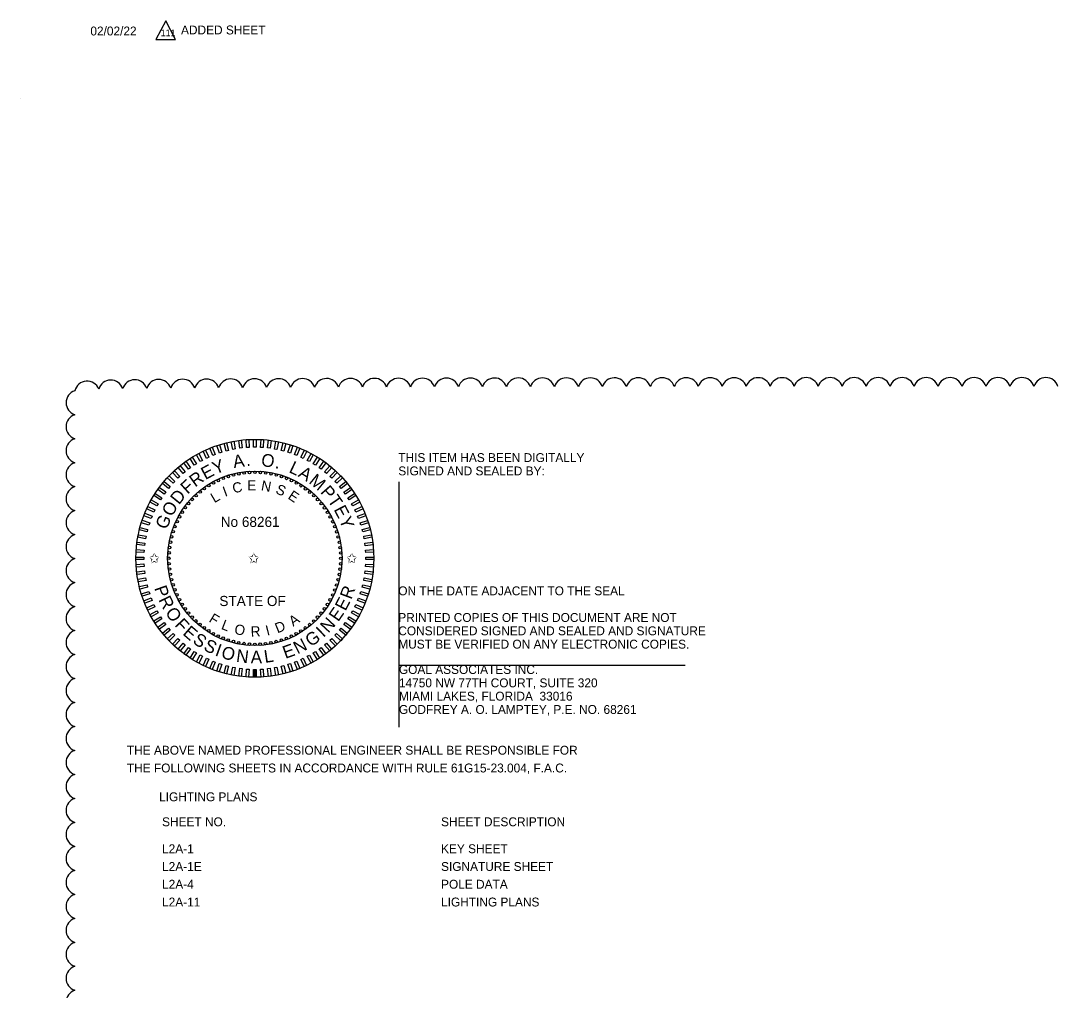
# Model space of a CAD drawing. Extents: x -811 to 10319, y -2309 to 9962.
# Drawn here: x -811.34 to -803.18, y -2252.59 to -2244.95 of the extents above; entities that cross this region are included whole.
import ezdxf

# ---------------------------------------------------------------- set-up
doc = ezdxf.new("R2010")
doc.units = 0
for name, color, linetype in [('AdhocPoint_dp', 7, 'Continuous'), ('PlotBorder_dp', 7, 'Continuous'), ('ScratchEle_dp', 7, 'Continuous'), ('SheetBorder_dp', 7, 'Continuous'), ('TextMinor', 7, 'Continuous'), ('TextMisc', 7, 'Continuous'), ('TextShtNo', 7, 'Continuous'), ('TextTitle', 7, 'Continuous')]:
    doc.layers.add(name, color=color, linetype=linetype)

msp = doc.modelspace()

# ---------------------------------------------------------------- linework, layer by layer
at = {"layer": 'AdhocPoint_dp'}
for p, q in [((-808.3546, -2248.5853), (-808.3546, -2250.52)), ((-808.3546, -2250.03), (-806.0979, -2250.03))]:
    msp.add_line(p, q, dxfattribs=at)
at = {"layer": 'ScratchEle_dp'}
for centre, radius, start, end in [((-810.8128, -2247.8912), 0.0992, 21.52097, 166.52097), ((-810.6255, -2247.883), 0.0991, 18.44241, 163.44241), ((-810.4367, -2247.8804), 0.0991, 18.17187, 163.17187), ((-810.2478, -2247.8784), 0.0991, 18.03188, 163.03188), ((-810.0588, -2247.8768), 0.0991, 17.94243, 162.94243), ((-809.8699, -2247.8754), 0.0991, 17.8789, 162.8789), ((-809.6809, -2247.8743), 0.0991, 17.83076, 162.83076), ((-809.4919, -2247.8732), 0.0991, 17.79266, 162.79266), ((-809.3029, -2247.8723), 0.0991, 17.76151, 162.76151), ((-809.1139, -2247.8715), 0.0991, 17.73544, 162.73544), ((-808.9249, -2247.8708), 0.0991, 17.7132, 162.7132), ((-808.736, -2247.8701), 0.0991, 17.69393, 162.69393), ((-808.547, -2247.8695), 0.0991, 17.67702, 162.67702), ((-808.358, -2247.8689), 0.0991, 17.66204, 162.66204), ((-808.169, -2247.8684), 0.0991, 17.64863, 162.64863), ((-807.98, -2247.8679), 0.0991, 17.63655, 162.63655), ((-807.791, -2247.8675), 0.0991, 17.62558, 162.62558), ((-807.602, -2247.8671), 0.0991, 17.61556, 162.61556), ((-807.413, -2247.8668), 0.0991, 17.60637, 162.60637), ((-807.224, -2247.8664), 0.0991, 17.5979, 162.5979), ((-807.035, -2247.8661), 0.0991, 17.59006, 162.59006), ((-806.846, -2247.8658), 0.0991, 17.58277, 162.58277), ((-806.657, -2247.8656), 0.0991, 17.57597, 162.57597), ((-806.468, -2247.8653), 0.0991, 17.56961, 162.56961), ((-806.279, -2247.8651), 0.0991, 17.56364, 162.56364), ((-806.09, -2247.8649), 0.0991, 17.55803, 162.55803), ((-805.901, -2247.8647), 0.0991, 17.55274, 162.55274), ((-805.712, -2247.8645), 0.0991, 17.54774, 162.54774), ((-805.523, -2247.8644), 0.0991, 17.54301, 162.54301), ((-805.334, -2247.8643), 0.0991, 17.53852, 162.53852), ((-805.145, -2247.8641), 0.0991, 17.53425, 162.53425), ((-804.956, -2247.864), 0.0991, 17.53018, 162.53018), ((-804.767, -2247.8639), 0.0991, 17.52631, 162.52631), ((-804.578, -2247.8639), 0.0991, 17.52261, 162.52261), ((-804.389, -2247.8638), 0.0991, 17.51907, 162.51907), ((-804.2, -2247.8637), 0.0991, 17.51569, 162.51569), ((-804.011, -2247.8637), 0.0991, 17.51244, 162.51244), ((-803.8221, -2247.8637), 0.0991, 17.50933, 162.50933), ((-803.6331, -2247.8636), 0.0991, 17.50633, 162.50633), ((-803.4441, -2247.8636), 0.0991, 17.50345, 162.50345), ((-803.2551, -2247.8636), 0.0991, 17.50077, 162.50077), ((-810.8794, -2247.9625), 0.099, 107.5, 252.5), ((-810.8794, -2248.1514), 0.0991, 107.5, 252.5), ((-810.8794, -2248.3405), 0.0991, 107.5, 252.5), ((-810.8794, -2248.5295), 0.0991, 107.5, 252.5), ((-810.8794, -2248.7185), 0.0991, 107.5, 252.5), ((-810.8794, -2248.9075), 0.0991, 107.5, 252.5), ((-810.8794, -2249.0965), 0.0991, 107.5, 252.5), ((-810.8794, -2249.2855), 0.0991, 107.5, 252.5), ((-810.8794, -2249.4745), 0.0991, 107.5, 252.5), ((-810.8794, -2249.6635), 0.0991, 107.5, 252.5), ((-810.8794, -2249.8525), 0.0991, 107.5, 252.5), ((-810.8794, -2250.0415), 0.0991, 107.5, 252.5), ((-810.8794, -2250.2305), 0.0991, 107.5, 252.5), ((-810.8794, -2250.4195), 0.0991, 107.5, 252.5), ((-810.8794, -2250.6085), 0.0991, 107.5, 252.5), ((-810.8794, -2250.7975), 0.0991, 107.5, 252.5), ((-810.8794, -2250.9865), 0.0991, 107.5, 252.5), ((-810.8794, -2251.1755), 0.0991, 107.5, 252.5), ((-810.8794, -2251.3645), 0.0991, 107.5, 252.5), ((-810.8794, -2251.5535), 0.0991, 107.5, 252.5), ((-810.8794, -2251.7425), 0.0991, 107.5, 252.5), ((-810.8794, -2251.9315), 0.0991, 107.5, 252.5), ((-810.8794, -2252.1205), 0.0991, 107.5, 252.5), ((-810.8794, -2252.3095), 0.0991, 107.5, 252.5), ((-810.8794, -2252.4985), 0.0991, 107.50047, 252.50047), ((-810.8794, -2252.6874), 0.0991, 107.52584, 252.52584)]:
    msp.add_arc(centre, radius, start, end, dxfattribs=at)
at = {"layer": 'SheetBorder_dp'}
msp.add_line((-811.3358, -2245.5621), (-811.3358, -2245.5621), dxfattribs=at)
at = {"layer": 'TextMinor'}
for radius in [0.9375, 0.6875]:
    msp.add_circle((-809.4901, -2249.1887), radius, dxfattribs=at)
at = {"layer": 'TextMisc'}
msp.add_lwpolyline([(-810.1928, -2244.9521), (-810.2698, -2245.1004), (-810.1158, -2245.1004)], close=True, dxfattribs=at)
at = {"layer": 'TextShtNo'}
for p, q in [((-809.5001, -2250.1262), (-809.5003, -2250.0637)), ((-809.4901, -2250.1262), (-809.4903, -2250.0637)), ((-809.4801, -2250.1261), (-809.4803, -2250.0636))]:
    msp.add_line(p, q, dxfattribs=at)
for points in [[(-809.4799, -2248.3136), (-809.5001, -2248.3136), (-809.5001, -2248.2512), (-809.4799, -2248.2512)], [(-809.8028, -2248.3713), (-809.8215, -2248.3788), (-809.8445, -2248.3207), (-809.8258, -2248.3133)], [(-809.7508, -2248.3533), (-809.77, -2248.3596), (-809.7893, -2248.3002), (-809.7701, -2248.2939)], [(-809.6979, -2248.3386), (-809.7174, -2248.3436), (-809.7329, -2248.2831), (-809.7134, -2248.2781)], [(-809.6441, -2248.3272), (-809.6639, -2248.331), (-809.6756, -2248.2697), (-809.6558, -2248.2659)], [(-809.5897, -2248.3193), (-809.6097, -2248.3218), (-809.6175, -2248.2599), (-809.5975, -2248.2573)], [(-809.5349, -2248.3147), (-809.555, -2248.316), (-809.559, -2248.2537), (-809.5388, -2248.2524)], [(-809.425, -2248.316), (-809.4452, -2248.3147), (-809.4412, -2248.2524), (-809.4211, -2248.2537)], [(-809.3703, -2248.3218), (-809.3904, -2248.3193), (-809.3825, -2248.2573), (-809.3625, -2248.2599)], [(-809.3162, -2248.3311), (-809.336, -2248.3273), (-809.3243, -2248.2659), (-809.3045, -2248.2697)], [(-809.2626, -2248.3437), (-809.2822, -2248.3387), (-809.2667, -2248.2782), (-809.2471, -2248.2832)], [(-809.21, -2248.3596), (-809.2292, -2248.3534), (-809.2099, -2248.294), (-809.1907, -2248.3002)], [(-809.1585, -2248.3788), (-809.1773, -2248.3714), (-809.1543, -2248.3134), (-809.1355, -2248.3208)], [(-809.9504, -2248.4444), (-809.9674, -2248.4552), (-810.0009, -2248.4025), (-809.9838, -2248.3917)], [(-809.9027, -2248.417), (-809.9204, -2248.4267), (-809.9505, -2248.372), (-809.9328, -2248.3623)], [(-809.8535, -2248.3926), (-809.8717, -2248.4012), (-809.8983, -2248.3447), (-809.8801, -2248.3361)], [(-809.1083, -2248.4013), (-809.1266, -2248.3927), (-809.1, -2248.3362), (-809.0817, -2248.3448)], [(-809.0596, -2248.4268), (-809.0773, -2248.4171), (-809.0473, -2248.3624), (-809.0296, -2248.3721)], [(-809.0127, -2248.4553), (-809.0297, -2248.4445), (-808.9962, -2248.3918), (-808.9792, -2248.4026)], [(-810.04, -2248.508), (-810.0556, -2248.5208), (-810.0954, -2248.4727), (-810.0798, -2248.4599)], [(-809.9962, -2248.4748), (-810.0125, -2248.4866), (-810.0492, -2248.4361), (-810.0329, -2248.4243)], [(-808.9676, -2248.4868), (-808.9839, -2248.4749), (-808.9472, -2248.4244), (-808.9308, -2248.4362)], [(-808.9245, -2248.5209), (-808.9401, -2248.5081), (-808.9003, -2248.46), (-808.8847, -2248.4728)], [(-810.121, -2248.5823), (-810.1348, -2248.597), (-810.1804, -2248.5542), (-810.1665, -2248.5395)], [(-810.0817, -2248.5438), (-810.0964, -2248.5577), (-810.1392, -2248.5121), (-810.1244, -2248.4983)], [(-808.8837, -2248.5578), (-808.8984, -2248.544), (-808.8557, -2248.4984), (-808.841, -2248.5123)], [(-808.8453, -2248.5971), (-808.8591, -2248.5824), (-808.8136, -2248.5396), (-808.7998, -2248.5544)], [(-810.192, -2248.6661), (-810.2039, -2248.6824), (-810.2544, -2248.6457), (-810.2426, -2248.6294)], [(-810.1579, -2248.6231), (-810.1707, -2248.6386), (-810.2188, -2248.5988), (-810.206, -2248.5833)], [(-808.8094, -2248.6388), (-808.8223, -2248.6232), (-808.7742, -2248.5834), (-808.7613, -2248.599)], [(-808.7762, -2248.6826), (-808.7881, -2248.6663), (-808.7376, -2248.6296), (-808.7257, -2248.6459)], [(-810.252, -2248.7582), (-810.2617, -2248.7759), (-810.3164, -2248.7458), (-810.3067, -2248.7281)], [(-810.2235, -2248.7112), (-810.2343, -2248.7283), (-810.287, -2248.6948), (-810.2762, -2248.6778)], [(-808.7459, -2248.7284), (-808.7567, -2248.7114), (-808.7039, -2248.6779), (-808.6931, -2248.695)], [(-808.7184, -2248.7761), (-808.7281, -2248.7584), (-808.6734, -2248.7283), (-808.6637, -2248.746)], [(-810.2775, -2248.8069), (-810.2861, -2248.8252), (-810.3426, -2248.7986), (-810.334, -2248.7803)], [(-808.694, -2248.8253), (-808.7026, -2248.8071), (-808.6461, -2248.7805), (-808.6375, -2248.7987)], [(-810.3192, -2248.9086), (-810.3254, -2248.9278), (-810.3848, -2248.9085), (-810.3786, -2248.8893)], [(-810.3, -2248.8571), (-810.3074, -2248.8759), (-810.3654, -2248.8529), (-810.358, -2248.8341)], [(-808.6728, -2248.876), (-808.6802, -2248.8573), (-808.6222, -2248.8343), (-808.6147, -2248.853)], [(-808.6548, -2248.928), (-808.661, -2248.9088), (-808.6016, -2248.8895), (-808.5954, -2248.9087)], [(-810.3351, -2248.9612), (-810.3401, -2248.9808), (-810.4006, -2248.9652), (-810.3956, -2248.9457)], [(-808.64, -2248.9809), (-808.6451, -2248.9614), (-808.5846, -2248.9459), (-808.5796, -2248.9654)], [(-810.357, -2249.0689), (-810.3595, -2249.0889), (-810.4215, -2249.0811), (-810.4189, -2249.0611)], [(-810.3477, -2249.0147), (-810.3515, -2249.0345), (-810.4129, -2249.0228), (-810.4091, -2249.003)], [(-808.6287, -2249.0347), (-808.6325, -2249.0149), (-808.5711, -2249.0032), (-808.5673, -2249.023)], [(-808.6207, -2249.0891), (-808.6232, -2249.0691), (-808.5613, -2249.0613), (-808.5588, -2249.0813)], [(-810.3628, -2249.1236), (-810.3641, -2249.1437), (-810.4264, -2249.1398), (-810.4251, -2249.1196)], [(-808.6162, -2249.1439), (-808.6174, -2249.1238), (-808.5551, -2249.1198), (-808.5539, -2249.14)], [(-810.3652, -2249.1785), (-810.3652, -2249.1987), (-810.4276, -2249.1987), (-810.4276, -2249.1785)], [(-808.6151, -2249.1989), (-808.6151, -2249.1787), (-808.5527, -2249.1787), (-808.5527, -2249.1989)], [(-810.3641, -2249.2335), (-810.3628, -2249.2536), (-810.4251, -2249.2575), (-810.4264, -2249.2374)], [(-810.3595, -2249.2882), (-810.357, -2249.3083), (-810.4189, -2249.3161), (-810.4215, -2249.2961)], [(-808.6233, -2249.3085), (-808.6207, -2249.2884), (-808.5588, -2249.2963), (-808.5613, -2249.3163)], [(-808.6175, -2249.2538), (-808.6162, -2249.2336), (-808.5539, -2249.2376), (-808.5551, -2249.2577)], [(-810.3516, -2249.3426), (-810.3478, -2249.3625), (-810.4091, -2249.3742), (-810.4129, -2249.3543)], [(-808.6325, -2249.3626), (-808.6287, -2249.3428), (-808.5674, -2249.3545), (-808.5712, -2249.3743)], [(-810.3402, -2249.3964), (-810.3352, -2249.416), (-810.3957, -2249.4315), (-810.4007, -2249.412)], [(-810.3255, -2249.4494), (-810.3192, -2249.4686), (-810.3786, -2249.4879), (-810.3849, -2249.4687)], [(-808.6611, -2249.4688), (-808.6548, -2249.4496), (-808.5954, -2249.4689), (-808.6017, -2249.4881)], [(-808.6451, -2249.4162), (-808.6401, -2249.3966), (-808.5796, -2249.4121), (-808.5846, -2249.4317)], [(-810.3075, -2249.5013), (-810.3, -2249.5201), (-810.3581, -2249.5431), (-810.3655, -2249.5243)], [(-810.2862, -2249.552), (-810.2776, -2249.5703), (-810.3341, -2249.5969), (-810.3427, -2249.5786)], [(-808.7027, -2249.5705), (-808.6941, -2249.5522), (-808.6376, -2249.5788), (-808.6462, -2249.5971)], [(-808.6803, -2249.5203), (-808.6729, -2249.5015), (-808.6148, -2249.5245), (-808.6222, -2249.5433)], [(-810.2618, -2249.6013), (-810.2521, -2249.619), (-810.3068, -2249.6491), (-810.3165, -2249.6314)], [(-808.7282, -2249.6192), (-808.7185, -2249.6015), (-808.6638, -2249.6315), (-808.6735, -2249.6492)], [(-810.2344, -2249.6489), (-810.2236, -2249.666), (-810.2763, -2249.6994), (-810.2871, -2249.6824)], [(-810.204, -2249.6948), (-810.1922, -2249.7111), (-810.2427, -2249.7478), (-810.2545, -2249.7315)], [(-808.7882, -2249.7112), (-808.7763, -2249.6949), (-808.7258, -2249.7316), (-808.7377, -2249.748)], [(-808.7568, -2249.6661), (-808.746, -2249.6491), (-808.6932, -2249.6826), (-808.704, -2249.6996)], [(-810.1708, -2249.7386), (-810.158, -2249.7541), (-810.2061, -2249.794), (-810.2189, -2249.7784)], [(-810.135, -2249.7803), (-810.1211, -2249.795), (-810.1667, -2249.8377), (-810.1805, -2249.823)], [(-808.8592, -2249.7951), (-808.8454, -2249.7804), (-808.7999, -2249.8231), (-808.8137, -2249.8378)], [(-808.8224, -2249.7543), (-808.8095, -2249.7387), (-808.7614, -2249.7785), (-808.7743, -2249.7941)], [(-810.0965, -2249.8196), (-810.0818, -2249.8334), (-810.1246, -2249.8789), (-810.1393, -2249.8651)], [(-810.0557, -2249.8564), (-810.0402, -2249.8693), (-810.08, -2249.9174), (-810.0955, -2249.9045)], [(-808.9402, -2249.8694), (-808.9247, -2249.8565), (-808.8848, -2249.9046), (-808.9004, -2249.9175)], [(-808.8985, -2249.8335), (-808.8838, -2249.8197), (-808.8411, -2249.8652), (-808.8558, -2249.879)], [(-810.0127, -2249.8906), (-809.9964, -2249.9025), (-810.0331, -2249.953), (-810.0494, -2249.9411)], [(-809.9676, -2249.922), (-809.9505, -2249.9328), (-809.984, -2249.9856), (-810.001, -2249.9748)], [(-809.9206, -2249.9506), (-809.9029, -2249.9603), (-809.933, -2250.015), (-809.9507, -2250.0053)], [(-809.0775, -2249.9604), (-809.0598, -2249.9507), (-809.0297, -2250.0054), (-809.0474, -2250.0151)], [(-809.0299, -2249.9329), (-809.0128, -2249.9221), (-808.9794, -2249.9749), (-808.9964, -2249.9857)], [(-808.984, -2249.9026), (-808.9677, -2249.8907), (-808.931, -2249.9412), (-808.9473, -2249.9531)], [(-809.8719, -2249.9761), (-809.8536, -2249.9847), (-809.8802, -2250.0412), (-809.8985, -2250.0326)], [(-809.8217, -2249.9985), (-809.8029, -2250.0059), (-809.8259, -2250.064), (-809.8447, -2250.0566)], [(-809.7702, -2250.0177), (-809.751, -2250.024), (-809.7703, -2250.0834), (-809.7895, -2250.0771)], [(-809.7176, -2250.0337), (-809.698, -2250.0387), (-809.7136, -2250.0992), (-809.7331, -2250.0942)], [(-809.2824, -2250.0388), (-809.2628, -2250.0337), (-809.2473, -2250.0942), (-809.2668, -2250.0992)], [(-809.2294, -2250.024), (-809.2102, -2250.0178), (-809.1909, -2250.0772), (-809.2101, -2250.0834)], [(-809.1775, -2250.006), (-809.1587, -2249.9986), (-809.1357, -2250.0566), (-809.1545, -2250.0641)], [(-809.1268, -2249.9848), (-809.1085, -2249.9762), (-809.0819, -2250.0327), (-809.1002, -2250.0413)], [(-809.6641, -2250.0463), (-809.6443, -2250.0501), (-809.656, -2250.1114), (-809.6758, -2250.1076)], [(-809.6099, -2250.0555), (-809.5899, -2250.0581), (-809.5977, -2250.12), (-809.6177, -2250.1175)], [(-809.5552, -2250.0613), (-809.5351, -2250.0626), (-809.539, -2250.1249), (-809.5592, -2250.1237)], [(-809.5003, -2250.0637), (-809.4801, -2250.0637), (-809.4801, -2250.1261), (-809.5003, -2250.1261)], [(-809.4453, -2250.0626), (-809.4252, -2250.0614), (-809.4213, -2250.1237), (-809.4414, -2250.1249)], [(-809.3906, -2250.0581), (-809.3705, -2250.0556), (-809.3627, -2250.1175), (-809.3827, -2250.12)], [(-809.3362, -2250.0501), (-809.3163, -2250.0463), (-809.3046, -2250.1077), (-809.3245, -2250.1115)]]:
    msp.add_lwpolyline(points, close=True, dxfattribs=at)
for centre in [(-809.7781, -2248.5754), (-809.739, -2248.5586), (-809.6989, -2248.5442), (-809.6581, -2248.5324), (-809.6165, -2248.5231), (-809.5745, -2248.5165), (-809.5321, -2248.5125), (-809.4896, -2248.5112), (-809.447, -2248.5126), (-809.4047, -2248.5166), (-809.3626, -2248.5233), (-809.3211, -2248.5326), (-809.2802, -2248.5445), (-809.2402, -2248.559), (-809.2012, -2248.5759), (-809.9215, -2248.6663), (-809.8879, -2248.6403), (-809.8527, -2248.6164), (-809.816, -2248.5947), (-809.1633, -2248.5953), (-809.1266, -2248.617), (-809.0915, -2248.6409), (-809.0579, -2248.667), (-809.9836, -2248.7245), (-809.9535, -2248.6944), (-809.026, -2248.6952), (-808.9959, -2248.7253), (-810.0618, -2248.8252), (-810.0379, -2248.79), (-810.0118, -2248.7564), (-808.9678, -2248.7573), (-808.9417, -2248.7909), (-808.9178, -2248.8261), (-810.1029, -2248.8997), (-810.0835, -2248.8618), (-808.8962, -2248.8628), (-808.8769, -2248.9007), (-810.1343, -2248.9788), (-810.1198, -2248.9388), (-808.86, -2248.9398), (-808.8456, -2248.9799), (-810.1555, -2249.0612), (-810.1462, -2249.0197), (-808.8338, -2249.0207), (-808.8245, -2249.0623), (-810.1662, -2249.1456), (-810.1622, -2249.1032), (-808.8179, -2249.1043), (-808.814, -2249.1467), (-810.1676, -2249.1881), (-810.1663, -2249.2307), (-808.814, -2249.2318), (-808.8127, -2249.1892), (-810.1623, -2249.273), (-810.1557, -2249.3151), (-808.8248, -2249.3162), (-808.8181, -2249.2741), (-810.1464, -2249.3566), (-810.1346, -2249.3975), (-808.846, -2249.3986), (-808.8341, -2249.3577), (-810.1202, -2249.4375), (-810.1034, -2249.4766), (-808.8774, -2249.4776), (-808.8604, -2249.4386), (-810.0841, -2249.5146), (-810.0624, -2249.5512), (-808.9184, -2249.5522), (-808.8967, -2249.5155), (-810.0385, -2249.5864), (-810.0125, -2249.6201), (-808.9685, -2249.6209), (-808.9424, -2249.5873), (-809.9844, -2249.652), (-809.9543, -2249.6821), (-809.9224, -2249.7103), (-809.0587, -2249.711), (-809.0268, -2249.6829), (-808.9967, -2249.6528), (-809.8888, -2249.7364), (-809.8536, -2249.7604), (-809.817, -2249.7821), (-809.7791, -2249.8014), (-809.2022, -2249.8019), (-809.1642, -2249.7826), (-809.1276, -2249.761), (-809.0924, -2249.7371), (-809.74, -2249.8184), (-809.7, -2249.8328), (-809.6591, -2249.8447), (-809.6176, -2249.854), (-809.5756, -2249.8607), (-809.5332, -2249.8648), (-809.4901, -2249.8662), (-809.4481, -2249.8648), (-809.4058, -2249.8609), (-809.3637, -2249.8543), (-809.3222, -2249.845), (-809.2813, -2249.8332), (-809.2413, -2249.8188)]:
    msp.add_circle(centre, 0.01, dxfattribs=at)

# ---------------------------------------------------------------- texts
at = {"layer": 'PlotBorder_dp'}
for s, p in [('THIS ITEM HAS BEEN DIGITALLY', (-808.3596, -2248.4301)), ('SIGNED AND SEALED BY:', (-808.3596, -2248.5351)), ('ON THE DATE ADJACENT TO THE SEAL', (-808.3596, -2249.4801)), ('PRINTED COPIES OF THIS DOCUMENT ARE NOT ', (-808.3596, -2249.6901)), ('CONSIDERED SIGNED AND SEALED AND SIGNATURE ', (-808.3596, -2249.7951)), ('MUST BE VERIFIED ON ANY ELECTRONIC COPIES.', (-808.3596, -2249.9001)), ('GOAL ASSOCIATES INC.', (-808.3546, -2250.1)), ('14750 NW 77TH COURT, SUITE 320', (-808.3546, -2250.205)), ('MIAMI LAKES, FLORIDA  33016', (-808.3546, -2250.31)), ('GODFREY A. O. LAMPTEY, P.E. NO. 68261', (-808.3546, -2250.415)), ('THE ABOVE NAMED PROFESSIONAL ENGINEER SHALL BE RESPONSIBLE FOR ', (-810.4987, -2250.7361)), ('THE FOLLOWING SHEETS IN ACCORDANCE WITH RULE 61G15-23.004, F.A.C.', (-810.4987, -2250.8761)), ('LIGHTING PLANS', (-810.245, -2251.1032))]:
    msp.add_text(s, height=0.07, dxfattribs=at).set_placement(p)
at = {"layer": 'TextMisc'}
msp.add_text('111', height=0.0525, rotation=360, dxfattribs=at).set_placement((-810.2325, -2245.074))
for s, p in [('SHEET NO.', (-810.2215, -2251.3001)), ('SHEET DESCRIPTION', (-808.0226, -2251.3001)), ('L2A-1', (-810.2215, -2251.5123)), ('KEY SHEET', (-808.0226, -2251.5123)), ('L2A-1E', (-810.2215, -2251.6523)), ('SIGNATURE SHEET', (-808.0226, -2251.6523)), ('L2A-4', (-810.2215, -2251.7923)), ('POLE DATA', (-808.0226, -2251.7923)), ('L2A-11', (-810.2215, -2251.9323)), ('LIGHTING PLANS', (-808.0226, -2251.9323))]:
    msp.add_text(s, height=0.07, dxfattribs=at).set_placement(p)
at = {"layer": 'TextShtNo'}
for s, height, rotation, p in [('Y', 0.1, 21.06329, (-809.8021, -2248.5293)), ('A', 0.1, 8.80884, (-809.6551, -2248.4781)), ('O', 0.1, 352.18771, (-809.4449, -2248.4606)), ('E', 0.1, 28.10553, (-809.8806, -2248.5725)), ('.', 0.1, 1.04184, (-809.5575, -2248.4623)), ('.', 0.1, 343.52684, (-809.3358, -2248.4757)), ('L', 0.1, 334.67271, (-809.2279, -2248.5079)), ('A', 0.1, 328.40959, (-809.1552, -2248.5406)), ('F', 0.1, 42.37723, (-810.0205, -2248.6878)), ('R', 0.1, 35.92688, (-809.9609, -2248.6314)), ('E', 0.08, 0.41861, (-809.5498, -2248.6536)), ('N', 0.08, 349.29143, (-809.4455, -2248.6521)), ('M', 0.1, 320.6426, (-809.0707, -2248.5918)), ('D', 0.1, 50.8569, (-810.0886, -2248.7715)), ('I', 0.08, 20.01168, (-809.7258, -2248.7046)), ('C', 0.08, 12.20255, (-809.6579, -2248.6771)), ('S', 0.08, 337.02207, (-809.3325, -2248.6739)), ('E', 0.08, 325.86633, (-809.2358, -2248.7141)), ('P', 0.1, 311.19658, (-808.9784, -2248.6687)), ('L', 0.08, 30.40215, (-809.8093, -2248.7551)), ('T', 0.1, 304.45632, (-808.9209, -2248.7324)), ('O', 0.1, 59.51777, (-810.1446, -2248.8663)), ('E', 0.1, 297.63152, (-808.8707, -2248.8033)), ('G', 0.1, 68.0518, (-810.1851, -2248.967)), ('Y', 0.1, 290.58928, (-808.8281, -2248.8821)), ('P', 0.1, 289.40551, (-810.2848, -2249.4233)), ('R', 0.1, 69.5134, (-808.7299, -2249.5184)), ('R', 0.1, 296.14576, (-810.2518, -2249.5149)), ('E', 0.1, 62.47116, (-808.7761, -2249.6091)), ('O', 0.1, 303.96711, (-810.2003, -2249.6155)), ('F', 0.08, 328.72408, (-809.8582, -2249.6853)), ('E', 0.1, 55.42892, (-808.833, -2249.6935)), ('F', 0.1, 312.62798, (-810.1279, -2249.7176)), ('E', 0.1, 319.07833, (-810.0645, -2249.7859)), ('L', 0.08, 339.29159, (-809.7609, -2249.7443)), ('O', 0.08, 349.68206, (-809.6562, -2249.7841)), ('I', 0.08, 14.20366, (-809.3941, -2249.7993)), ('D', 0.08, 22.01279, (-809.312, -2249.7806)), ('A', 0.08, 34.49917, (-809.1883, -2249.7281)), ('N', 0.1, 47.17876, (-808.9123, -2249.7825)), ('S', 0.1, 326.12056, (-809.9869, -2249.8518)), ('R', 0.08, 2.33977, (-809.5217, -2249.806)), ('G', 0.1, 35.11153, (-809.0492, -2249.8902)), ('I', 0.1, 43.64556, (-808.9499, -2249.817)), ('S', 0.1, 333.193, (-809.9015, -2249.9079)), ('I', 0.1, 340.26543, (-809.8098, -2249.9531)), ('O', 0.1, 343.79863, (-809.7621, -2249.9714)), ('E', 0.1, 19.81912, (-809.2498, -2249.9817)), ('N', 0.1, 26.86136, (-809.1544, -2249.9462)), ('N', 0.1, 352.45949, (-809.6411, -2250.0034)), ('A', 0.1, 0.70966, (-809.5227, -2250.0166)), ('L', 0.1, 8.47665, (-809.4105, -2250.0134))]:
    msp.add_text(s, height=height, rotation=rotation, dxfattribs=at).set_placement(p)
for s, p in [('No 68261', (-809.7591, -2248.9414)), ('✩', (-810.3251, -2249.2266)), ('✩', (-809.5404, -2249.2266)), ('✩', (-808.7685, -2249.2266)), ('STATE OF', (-809.7698, -2249.5649))]:
    msp.add_text(s, height=0.08, dxfattribs=at).set_placement(p)
at = {"layer": 'TextTitle'}
for s, p in [('ADDED SHEET', (-810.0721, -2245.0602)), ('02/02/22', (-810.7866, -2245.0683))]:
    msp.add_text(s, height=0.07, rotation=0, dxfattribs=at).set_placement(p)

doc.saveas('drawing.dxf')
